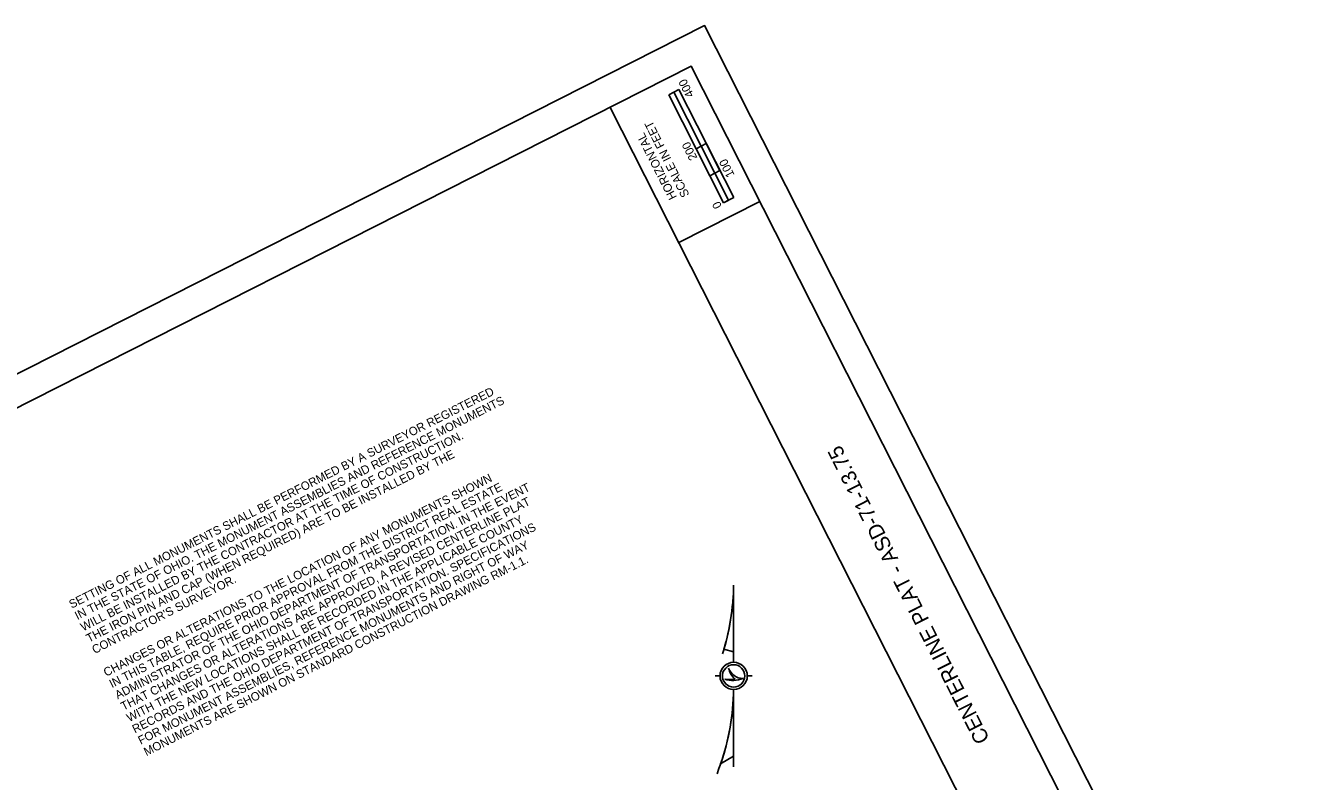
# Model space of a CAD drawing. Extents: x -5125 to 2930, y -3746 to 3253.
# Drawn here: x -1300 to 2930, y 757 to 3253 of the extents above; entities that cross this region are included whole.
import ezdxf

# ---------------------------------------------------------------- set-up
doc = ezdxf.new("R2010")
doc.units = 0
for name, color, linetype in [('SC_Scratch1', 7, 'Continuous'), ('SV_P_Mon_Cells_Set', 7, 'Continuous'), ('SV_X_Control_Cells_Found', 7, 'Continuous'), ('SV_X_Random_Point', 7, 'Continuous')]:
    doc.layers.add(name, color=color, linetype=linetype)

msp = doc.modelspace()

# ---------------------------------------------------------------- linework, layer by layer
at = {"layer": 'SV_P_Mon_Cells_Set'}
for p, q in [((2528.1, -763.3), (629, 2982.9)), ((855.1, 2536.9), (1122.7, 2672.5))]:
    msp.add_line(p, q, dxfattribs=at)
msp.add_lwpolyline([(-4811.8, 224.7), (896.6, 3118.5), (2795.7, -627.6), (-2912.7, -3521.5)], close=True, dxfattribs=at)
at = {"layer": 'SV_X_Control_Cells_Found'}
msp.add_lwpolyline([(-3135.1, -3746.3), (2930.1, -671.6), (940.6, 3252.9), (-5124.6, 178.2)], close=True, dxfattribs=at)
at = {"layer": 'SV_X_Random_Point'}
for p, q in [((855.7, 3041.7), (822.3, 3024.8)), ((822.3, 3024.8), (838.9, 3033.2)), ((1003.1, 2668), (822.3, 3024.8)), ((912.7, 2846.4), (822.3, 3024.8)), ((838.9, 3033.2), (839.1, 3033.3)), ((839.1, 3033.3), (929.5, 2854.9)), ((855.7, 3041.7), (1036.6, 2685)), ((929.5, 2854.9), (912.7, 2846.4)), ((946, 2863.3), (929.3, 2854.8)), ((929.3, 2854.8), (974.6, 2765.6)), ((991.2, 2774.1), (946, 2863.3)), ((974.6, 2765.6), (957.9, 2757.2)), ((957.9, 2757.2), (1003.1, 2668)), ((974.6, 2765.6), (991.2, 2774.1)), ((1019.8, 2676.4), (974.6, 2765.6)), ((1036.6, 2685), (1003.1, 2668)), ((1003.1, 2668), (1019.8, 2676.4)), ((1036.5, 1150.4), (1036.5, 1405.4)), ((1004.6, 1193.5), (1036.5, 1184.8)), ((975.5, 1105.4), (991.5, 1105.4)), ((1081.5, 1105.4), (1097.5, 1105.4)), ((1036.5, 805.4), (1036.5, 1060.4)), ((1036.5, 840.4), (993.6, 814.7))]:
    msp.add_line(p, q, dxfattribs=at)
for points in [[(1004.4, 1193.5), (1004.6, 1193.5), (1036.5, 1184.8), (1036.5, 1405.4)], [(993.6, 814.7), (1036.5, 840.4), (1036.5, 1060.4)]]:
    msp.add_lwpolyline(points, dxfattribs=at)
for radius in [45, 37]:
    msp.add_circle((1036.5, 1105.4), radius, dxfattribs=at)
for centre, radius, start, end in [((248, 1416.5), 788.5, 342.4153, 359.1947), ((248, 1416.5), 788.5, 343.5754, 359.1947), ((1068, 1148), 51, 199.1575, 269.3709), ((1089.7, 1147.2), 71.7, 192.8556, 227.3141), ((248, 1071.5), 788.5, 338.5054, 359.1947), ((248, 1071.5), 788.5, 340.9936, 359.1947), ((1034.3, 1181.2), 90.5, 252.4874, 291.486), ((1025.5, 1207.7), 114.3, 260.7277, 277.8734)]:
    msp.add_arc(centre, radius, start, end, dxfattribs=at)

# ---------------------------------------------------------------- texts
at = {"layer": 'SC_Scratch1'}
for s, p in [('SETTING OF ALL MONUMENTS SHALL BE PERFORMED BY A SURVEYOR REGISTERED', (-1148.4, 1327.3)), ('IN THE STATE OF OHIO. THE MONUMENT ASSEMBLIES AND REFERENCE MONUMENTS', (-1129.4, 1289.9)), ('WILL BE INSTALLED BY THE CONTRACTOR AT THE TIME OF CONSTRUCTION.', (-1110.5, 1252.4)), ('THE IRON PIN AND CAP (WHEN REQUIRED) ARE TO BE INSTALLED BY THE', (-1091.5, 1214.9)), ('CHANGES OR ALTERATIONS TO THE LOCATION OF ANY MONUMENTS SHOWN ', (-1034.5, 1102.5)), ('IN THIS TABLE, REQUIRE PRIOR APPROVAL FROM THE DISTRICT REAL ESTATE ', (-1015.5, 1065.1)), ('ADMINISTRATOR OF THE OHIO DEPARTMENT OF TRANSPORTATION. IN THE EVENT', (-996.5, 1027.6)), ('THAT CHANGES OR ALTERATIONS ARE APPROVED, A REVISED CENTERLINE PLAT', (-977.5, 990.2)), ('WITH THE NEW LOCATIONS SHALL BE RECORDED IN THE APPLICABLE COUNTY', (-958.5, 952.7)), ('RECORDS AND THE OHIO DEPARTMENT OF TRANSPORTATION. SPECIFICATIONS', (-939.5, 915.2)), ('FOR MONUMENT ASSEMBLIES, REFERENCE MONUMENTS AND RIGHT OF WAY', (-920.5, 877.8)), ('MONUMENTS ARE SHOWN ON STANDARD CONSTRUCTION DRAWING RM-1.1.', (-901.6, 840.3)), ("CONTRACTOR'S SURVEYOR.", (-1072.5, 1177.5))]:
    msp.add_text(s, height=28, rotation=26.8824, dxfattribs=at).set_placement(p)
at = {"layer": 'SV_X_Random_Point'}
for s, height, p in [('400', 28, (906.4, 3024.1)), ('SCALE IN FEET', 28, (891.3, 2694.4)), ('HORIZONTAL', 28, (849.8, 2686.5)), ('200', 28, (917.4, 2816.6)), ('100', 28, (1040.2, 2760.1)), ('0', 28, (998.4, 2656.9)), ('CENTERLINE PLAT - ASD-71-13.75', 50, (1882.8, 896.6))]:
    msp.add_text(s, height=height, rotation=116.8824, dxfattribs=at).set_placement(p)

doc.saveas('drawing.dxf')
